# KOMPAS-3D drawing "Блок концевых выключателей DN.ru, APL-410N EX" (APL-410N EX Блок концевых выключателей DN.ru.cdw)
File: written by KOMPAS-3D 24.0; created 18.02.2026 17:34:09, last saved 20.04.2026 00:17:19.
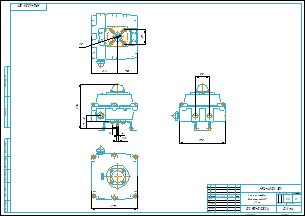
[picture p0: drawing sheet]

Document properties: Автор: R2D2; Форматы листов документа: A2; Полное имя файла: APL-410N Блок концевых выключателей DN.ru.m3d; Масса: 1.1; Наименование: Блок концевых выключателей DN.ru; Количество листов документа: 1; Примечание: D290-00324

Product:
- Part/product: Блок концевых выключателей DN.ru  | designation APL-410N EX
    Масса: 1.1
    Раздел спецификации: Прочие изделия
    Примечание: D290-00324

Referenced files in E:\Работа\Зайцев\Для компаса\: чертеж DN.ru А3.cdt
Referenced files in E:\Работа\Зайцев\Аксессуары для пневмоприводов\Блок концевых выключателей DN.ru\APL-410N EX Блок концевых выключателей DN.ru\: APL-410N Блок концевых выключателей DN.ru.m3d
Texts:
  чертеж DN.ru А3.cdt
  Блок концевых
  выключателей
  APL-410N EX
  Блок концевых выключателей DN.ru
  APL-410N EX Блок концевых выключателей DN.ru
Dimensions and other numbers on the sheet: 1:2; 0; 1; 2; 1,1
